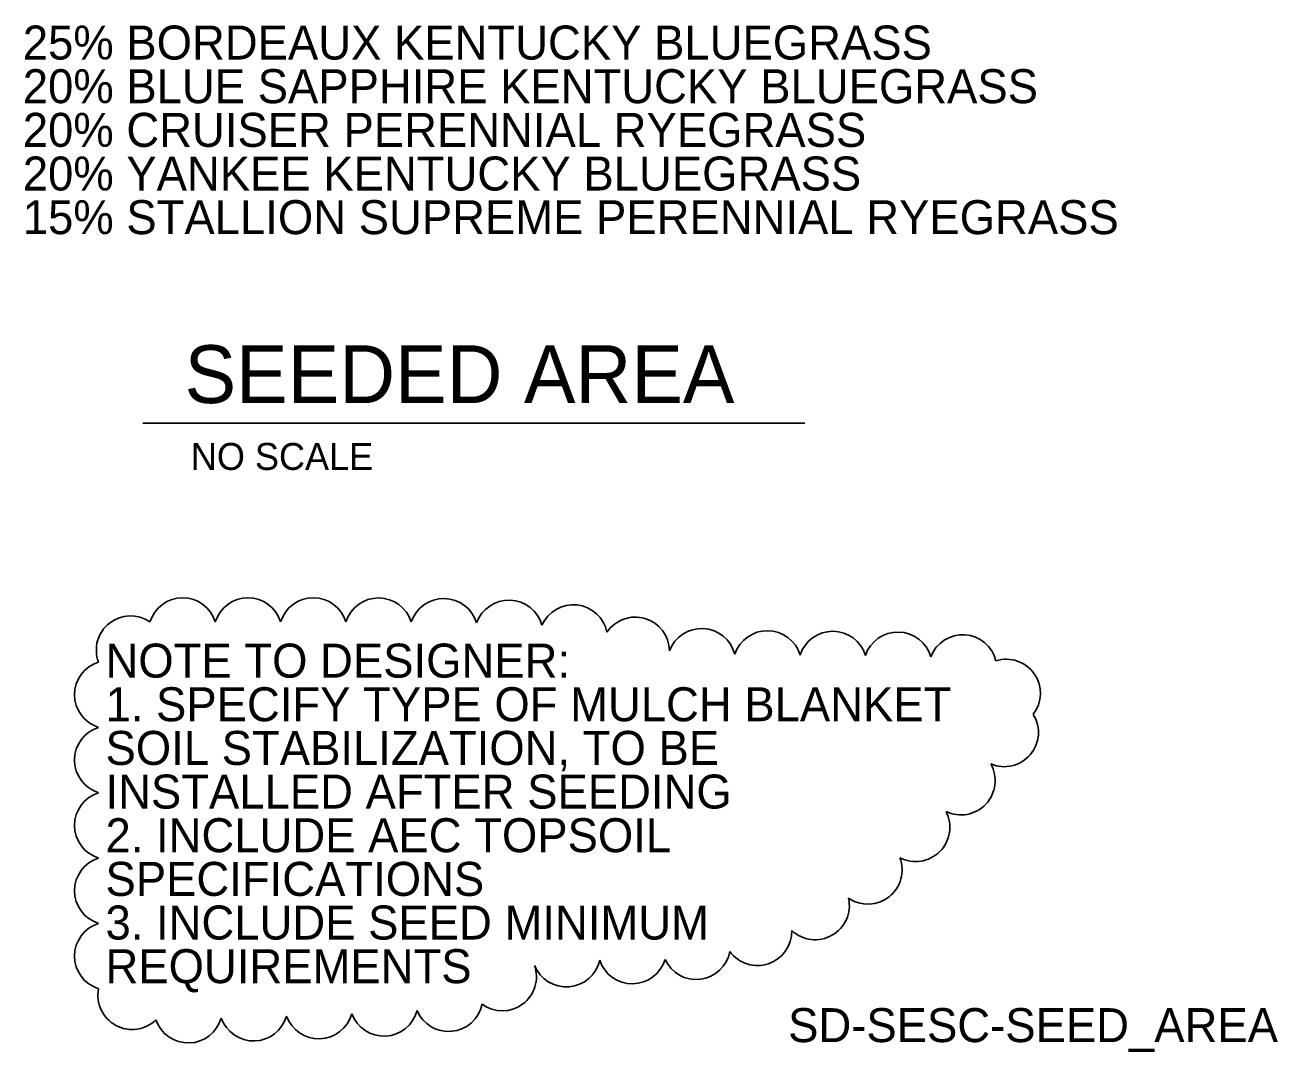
# Model space of a CAD drawing. Extents: x 9966.4 to 10027.9, y 9879.4 to 9942.8.
# Drawn here: x 9981.99 to 10020.48, y 9879.38 to 9910.93 of the extents above; entities that cross this region are included whole.
import ezdxf

# ---------------------------------------------------------------- set-up
doc = ezdxf.new("R2010")
doc.units = 0
doc.layers.add('G-ANNO-TEXT', color=7, linetype='Continuous')
doc.layers.add('G-ANNO-TTXT', color=7, linetype='Continuous')

msp = doc.modelspace()

# ---------------------------------------------------------------- linework, layer by layer
at = {"layer": 'G-ANNO-TEXT'}
msp.add_line((9985.608, 9898.695), (10005.942, 9898.695), dxfattribs=at)
at = {"layer": 'G-ANNO-TTXT'}
for centre, radius, start, end in [((9986.831, 9892.278), 1.052, 17.5, 162.5), ((9988.838, 9892.278), 1.052, 17.5, 162.5), ((9990.845, 9892.278), 1.052, 17.5, 162.5), ((9992.852, 9892.276), 1.052, 17.3548, 162.3548), ((9994.855, 9892.258), 1.052, 16.6629, 161.6629), ((9996.854, 9892.207), 1.052, 15.3724, 160.3724), ((9998.833, 9892.065), 1.052, 11.4177, 156.4177), ((9985.231, 9891.727), 1.052, 55.5131, 200.5131), ((10000.738, 9891.686), 1.052, 1.082, 146.082), ((10002.775, 9891.336), 1.052, 14.4173, 159.4173), ((10004.794, 9891.268), 1.052, 16.7544, 161.7544), ((10006.804, 9891.251), 1.052, 17.2372, 162.2372), ((10008.806, 9891.226), 1.052, 16.3269, 161.3269), ((10010.798, 9891.143), 1.052, 13.9509, 158.9509), ((9984.562, 9890.355), 1.052, 107.5, 252.5), ((10012.133, 9890.394), 1.051, 322.3737, 107.3737), ((10012.072, 9889.196), 1.052, 246.8796, 31.8796), ((9984.562, 9888.348), 1.052, 107.5, 252.5), ((10010.741, 9887.713), 1.052, 244.2765, 29.2765), ((9984.562, 9886.34), 1.052, 107.5, 252.5), ((10009.35, 9886.28), 1.052, 242.4392, 27.4392), ((9984.562, 9884.333), 1.052, 107.5, 252.5), ((10007.881, 9884.971), 1.052, 235.9479, 20.9479), ((10006.262, 9883.88), 1.052, 227.0404, 12.0404), ((9984.562, 9882.326), 1.052, 107.5, 252.5), ((10004.493, 9883.086), 1.052, 216.2754, 1.2754), ((10002.61, 9882.658), 1.052, 204.3671, 349.3671), ((9996.649, 9881.695), 1.052, 234.0167, 19.0167), ((9998.619, 9882.432), 1.053, 202.0191, 347.0191), ((10000.644, 9882.526), 1.052, 198.3049, 343.3049), ((9985.278, 9881.121), 1.052, 168.9881, 313.9881), ((9995.001, 9881.061), 1.052, 203.0517, 348.0517), ((9987.003, 9880.709), 1.052, 199.1139, 344.1139), ((9989.009, 9880.769), 1.052, 199.2978, 344.2978), ((9991.014, 9880.834), 1.052, 199.4491, 344.4491), ((9993.015, 9880.917), 1.052, 200.2747, 345.2747)]:
    msp.add_arc(centre, radius, start, end, dxfattribs=at)

# ---------------------------------------------------------------- texts
at = {"layer": 'G-ANNO-TEXT'}
for s, height, p in [('25% BORDEAUX KENTUCKY BLUEGRASS', 1.044, (9981.92, 9909.866)), ('20% BLUE SAPPHIRE KENTUCKY BLUEGRASS', 1.044, (9981.92, 9908.525)), ('20% CRUISER PERENNIAL RYEGRASS', 1.044, (9981.92, 9907.184)), ('20% YANKEE KENTUCKY BLUEGRASS', 1.044, (9981.92, 9905.843)), ('15% STALLION SUPREME PERENNIAL RYEGRASS', 1.044, (9981.92, 9904.502)), ('SEEDED AREA', 1.776, (9986.89, 9899.313)), ('NO SCALE', 0.828, (9987.084, 9897.26)), ('NOTE TO DESIGNER:', 1.044, (9984.461, 9890.88)), ('1. SPECIFY TYPE OF MULCH BLANKET ', 1.044, (9984.461, 9889.539)), ('SOIL STABILIZATION, TO BE ', 1.044, (9984.461, 9888.198)), ('INSTALLED AFTER SEEDING', 1.044, (9984.461, 9886.857)), ('2. INCLUDE AEC TOPSOIL ', 1.044, (9984.461, 9885.516)), ('SPECIFICATIONS', 1.044, (9984.461, 9884.175)), ('3. INCLUDE SEED MINIMUM ', 1.044, (9984.461, 9882.834)), ('REQUIREMENTS', 1.044, (9984.461, 9881.493)), ('SD-SESC-SEED_AREA', 1.044, (10005.433, 9879.682))]:
    msp.add_text(s, height=height, dxfattribs=at).set_placement(p)

doc.saveas('drawing.dxf')
